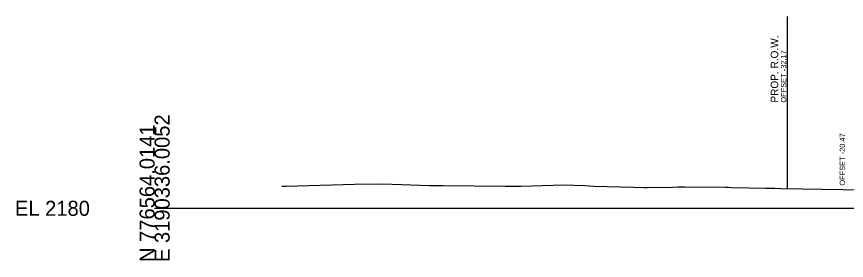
# Model space of a CAD drawing. Extents: x -26 to 303, y -10 to 13517.
# Drawn here: x -25.7 to 128.8, y 11490.3 to 11535.7 of the extents above; entities that cross this region are included whole.
import ezdxf

# ---------------------------------------------------------------- set-up
doc = ezdxf.new("R2010")
doc.units = 0
for name, color, linetype in [('DESIGN - ROW - Right-of-Way and Easement Labels', 7, 'Continuous'), ('DESIGN - ROW - Right-of-Way Linework', 7, 'Continuous'), ('DESIGN - SHEET - Light Grid', 7, 'Continuous'), ('DESIGN - TYPICAL - Slope Tie Text', 7, 'Continuous'), ('SURVEY - GROUND - Top of Ground', 7, 'Continuous')]:
    doc.layers.add(name, color=color, linetype=linetype)

msp = doc.modelspace()

# ---------------------------------------------------------------- linework, layer by layer
at = {"layer": 'DESIGN - ROW - Right-of-Way Linework'}
msp.add_line((117.83, 11503.67), (117.83, 11535.67), dxfattribs=at)
at = {"layer": 'DESIGN - SHEET - Light Grid'}
msp.add_line((0, 11500), (150, 11500), dxfattribs=at)
at = {"layer": 'SURVEY - GROUND - Top of Ground'}
msp.add_line((37.23, 11504.47), (42.47, 11504.58), dxfattribs=at)
for points in [[(42.47, 11504.58), (51.18, 11504.26), (52.24, 11504.25), (53.63, 11504.23), (65.28, 11504.1), (68.21, 11504.1), (76.19, 11504.36), (80.11, 11504.26), (81.7, 11504.09), (89.2, 11503.95), (91.04, 11503.9), (91.66, 11503.89), (96.37, 11503.96), (97.47, 11504), (98.67, 11503.98), (106.21, 11503.91), (106.82, 11503.94), (107.44, 11503.89), (113.7, 11503.75), (115.45, 11503.74), (116.61, 11503.69), (128.11, 11503.49), (131.98, 11503.42)], [(23.7, 11504.13), (24.49, 11504.12), (37.23, 11504.47)]]:
    msp.add_lwpolyline(points, dxfattribs=at)

# ---------------------------------------------------------------- texts
at = {"layer": 'DESIGN - ROW - Right-of-Way and Easement Labels'}
for s, height, p in [('PROP. R.O.W.', 1.4, (116.08, 11519.67)), ('OFFSET -32.17', 1, (117.58, 11519.67))]:
    msp.add_text(s, height=height, rotation=90, dxfattribs=at).set_placement(p)
at = {"layer": 'DESIGN - SHEET - Light Grid'}
for s, p in [('E 3190336.0052', (2.8, 11490)), ('N 776564.0141', (0, 11490))]:
    msp.add_text(s, height=2.8, rotation=90, dxfattribs=at).set_placement(p)
msp.add_text('EL 2180', height=2.8, dxfattribs=at).set_placement((-26, 11498.6))
at = {"layer": 'DESIGN - TYPICAL - Slope Tie Text'}
msp.add_text('OFFSET -20.47', height=1, rotation=90, dxfattribs=at).set_placement((128.53, 11504.22))

doc.saveas('drawing.dxf')
